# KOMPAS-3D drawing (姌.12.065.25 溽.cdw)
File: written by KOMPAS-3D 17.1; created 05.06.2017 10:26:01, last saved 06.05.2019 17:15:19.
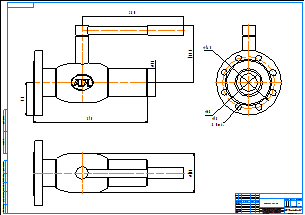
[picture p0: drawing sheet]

Sheet 1: A1, landscape

Title block, sheet 1: name: КШ.12.065.25 фс; material: Внимание! Данный продукт является объектом авторского права ООО «Торговый Дом АДЛ». / Запрещается изменение, копирование, распространение / (в том числе путем копирования на другие сайты и ресурсы в Интернете) / или любое иное использование информации и объектов без предварительного / согласия правообладателя (ООО «Торговый Дом АДЛ»).; sheets: 1; organisation: ООО "Торговый дом АДЛ"; sheet format: A1; stored path: C:\Users\kka\KOMPAS_Work\Модели кранов для исследований\Все краники\Редуцированный резьба-сварка ШК БИВАЛ\КШ.02.015.40 рс.cdw

Views: Вид 1, Проекционный вид 4, Проекционный вид 5
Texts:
  Klimkovich
  ADL
Dimensions and other numbers on the sheet: 280; 76; 315; 159,3; 145; 90; 68; 18; 8 Отв.; 108; 1:1; 1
